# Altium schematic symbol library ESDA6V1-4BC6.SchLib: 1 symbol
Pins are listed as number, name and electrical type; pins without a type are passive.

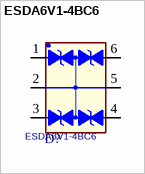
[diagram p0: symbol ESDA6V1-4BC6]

## ESDA6V1-4BC6
designator D?
footprint ST_SOT23-6L
pins: 1, 2, 3, 4, 5, 6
